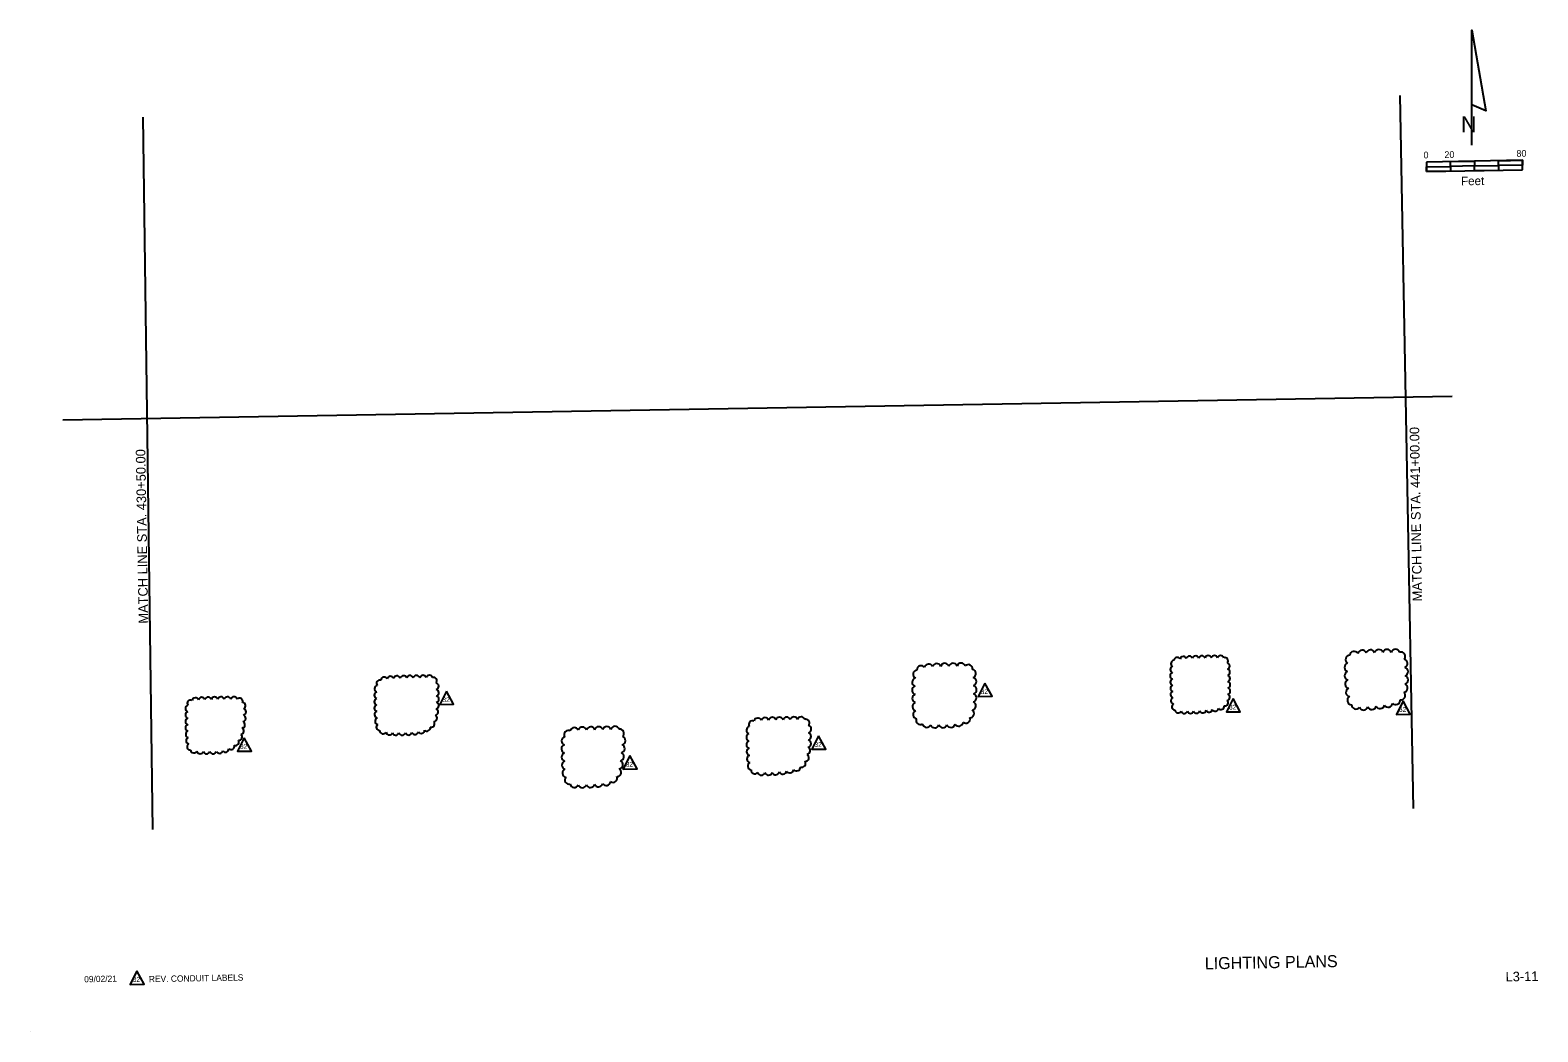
# Model space of a CAD drawing. Extents: x 921361 to 922617, y 636610 to 637445.
import ezdxf

# ---------------------------------------------------------------- set-up
doc = ezdxf.new("R2010")
doc.units = 0
for name, color, linetype in [('ActivePointCell_dp', 7, 'Continuous'), ('AdhocPoint_dp', 7, 'Continuous'), ('Cloud_dp', 7, 'Continuous'), ('MatchLines_dp', 7, 'Continuous'), ('NorthArw_dp', 7, 'Continuous'), ('Scale_dp', 7, 'Continuous'), ('TextLabel', 7, 'Continuous'), ('TextMisc', 7, 'Continuous'), ('TextNotes', 7, 'Continuous'), ('TextShtNo', 7, 'Continuous')]:
    doc.layers.add(name, color=color, linetype=linetype)

msp = doc.modelspace()

# ---------------------------------------------------------------- linework, layer by layer
at = {"layer": 'ActivePointCell_dp'}
msp.add_line((922545.7, 637139.8), (921387.8, 637119.9), dxfattribs=at)
at = {"layer": 'AdhocPoint_dp'}
msp.add_line((921360.5, 636610.2), (921360.5, 636610.2), dxfattribs=at)
at = {"layer": 'Cloud_dp'}
for points in [[(921707.6, 636894.2), (921702, 636883), (921713.5, 636883.2)], [(922156.2, 636900.9), (922150.6, 636889.7), (922162.2, 636889.9)], [(922363.2, 636888), (922357.6, 636876.8), (922369.1, 636877)], [(922504.8, 636886), (922499.3, 636874.8), (922510.8, 636875)], [(921538.9, 636855.3), (921533.3, 636844.1), (921544.9, 636844.2)], [(922017.7, 636856.9), (922012.1, 636845.7), (922023.7, 636845.9)], [(921860.4, 636840.4), (921854.8, 636829.2), (921866.4, 636829.4)]]:
    msp.add_lwpolyline(points, close=True, dxfattribs=at)
for centre, radius, start, end in [((922464, 636923.7), 3.64, 30.1798, 175.1798), ((922470.7, 636924.7), 3.64, 21.6099, 166.6099), ((922477.6, 636925), 3.64, 19.0739, 164.0739), ((922484.6, 636925.2), 3.64, 18.4841, 163.4841), ((922491.5, 636925.3), 3.64, 18.4841, 163.4841), ((922498.5, 636925.4), 3.64, 18.4841, 163.4841), ((922503, 636923.1), 3.64, 322.1453, 107.1453), ((922103.1, 636911.8), 3.56, 36.9318, 181.9318), ((922109.4, 636913.2), 3.56, 22.7645, 167.7645), ((922116.1, 636913.6), 3.56, 19.3571, 164.3571), ((922122.9, 636913.8), 3.56, 18.4841, 163.4841), ((922129.7, 636913.9), 3.56, 18.4841, 163.4841), ((922136.5, 636914), 3.56, 18.4841, 163.4841), ((922142.5, 636912.7), 3.56, 352.2854, 137.2854), ((922313.5, 636912.1), 2.74, 106.6056, 251.6056), ((922314.1, 636917.1), 2.74, 95.2077, 240.2077), ((922316.5, 636919.6), 2.74, 29.5227, 174.5227), ((922321.6, 636920.3), 2.74, 22.0992, 167.0992), ((922326.8, 636920.6), 2.74, 19.9037, 164.9037), ((922332, 636920.8), 2.74, 18.7453, 163.7453), ((922337.2, 636920.9), 2.74, 18.4841, 163.4841), ((922342.4, 636921), 2.74, 18.4841, 163.4841), ((922347.6, 636921.1), 2.74, 18.4841, 163.4841), ((922352.8, 636921.1), 2.74, 18.4841, 163.4841), ((922356.2, 636919.4), 2.74, 321.0005, 106.0005), ((922357.6, 636915), 2.74, 289.5103, 74.5103), ((922459.6, 636913.9), 3.64, 107.3116, 252.3116), ((922460.5, 636920.4), 3.64, 91.6372, 236.6372), ((922504.9, 636917.3), 3.64, 290.4209, 75.4209), ((922505.3, 636910.4), 3.64, 289.9256, 74.9256), ((921652, 636900.6), 2.83, 73.5324, 218.5324), ((921655.7, 636903), 2.84, 28.2478, 173.2478), ((921660.9, 636903.7), 2.83, 22.418, 167.418), ((921666.3, 636904.1), 2.83, 20.0853, 165.0853), ((921671.7, 636904.2), 2.83, 18.771, 163.771), ((921677.1, 636904.4), 2.83, 18.4841, 163.4841), ((921682.5, 636904.4), 2.83, 18.4841, 163.4841), ((921687.9, 636904.5), 2.83, 18.4841, 163.4841), ((921693.3, 636904.6), 2.83, 18.4841, 163.4841), ((921696.7, 636902.8), 2.83, 320.3694, 105.3694), ((921698.2, 636898.3), 2.83, 289.3685, 74.3685), ((922099.2, 636901.6), 3.56, 105.3663, 250.3663), ((922100, 636908.2), 3.56, 96.486, 241.486), ((922145.2, 636908.8), 3.56, 292.6182, 77.6182), ((922145.6, 636902.1), 3.56, 289.5181, 74.5181), ((922313.4, 636906.9), 2.74, 107.7156, 252.7156), ((922313.5, 636901.7), 2.74, 108.2731, 253.2731), ((922357.8, 636909.8), 2.74, 289.5103, 74.5103), ((922357.9, 636904.6), 2.74, 289.228, 74.228), ((922358, 636899.4), 2.74, 288.0027, 73.0027), ((922459.7, 636907), 3.64, 109.9491, 254.9491), ((922460.1, 636900.1), 3.64, 111.5337, 256.5337), ((922505.4, 636903.5), 3.64, 286.7675, 71.7675), ((921498.2, 636885.8), 2.82, 22.4167, 167.4167), ((921503.5, 636886.2), 2.82, 19.9475, 164.9475), ((921508.9, 636886.4), 2.82, 18.8576, 163.8576), ((921514.3, 636886.5), 2.82, 18.4841, 163.4841), ((921519.6, 636886.6), 2.82, 18.4841, 163.4841), ((921525, 636886.6), 2.82, 18.4841, 163.4841), ((921530.4, 636886.7), 2.82, 18.4841, 163.4841), ((921650.2, 636890.7), 2.83, 106.1055, 251.1055), ((921650.4, 636896.1), 2.83, 102.597, 247.597), ((921698.3, 636892.9), 2.83, 289.363, 74.363), ((921698.4, 636887.5), 2.83, 287.8949, 72.8949), ((922099.1, 636894.9), 3.56, 107.5915, 252.5915), ((922099.2, 636888.1), 3.56, 108.7605, 253.7605), ((922145.7, 636888.6), 3.56, 285.3566, 70.3566), ((922145.8, 636895.3), 3.56, 287.9842, 72.9842), ((922313.6, 636896.5), 2.74, 108.789, 253.789), ((922313.7, 636891.3), 2.74, 109.6972, 254.6972), ((922314, 636886.1), 2.74, 111.4666, 256.4666), ((922357.7, 636889), 2.74, 282.053, 67.053), ((922358, 636894.2), 2.74, 286.0076, 71.0076), ((922460.8, 636893.2), 3.64, 114.1871, 259.1871), ((922462, 636886.5), 3.64, 122.1504, 267.1504), ((922503, 636890.6), 3.64, 259.1914, 44.1914), ((922504.9, 636896.7), 3.64, 280.4674, 65.4674), ((921492.7, 636874.3), 2.82, 107.7468, 252.7468), ((921492.7, 636879.7), 2.82, 106.561, 251.561), ((921494.3, 636883.9), 2.82, 66.4572, 211.4572), ((921534.9, 636885.5), 2.82, 345.7741, 130.7741), ((921537.3, 636882), 2.82, 298.4484, 83.4484), ((921537.7, 636876.9), 2.82, 285.4432, 70.4432), ((921650.1, 636885.3), 2.83, 107.7278, 252.7278), ((921650.2, 636880), 2.83, 108.8515, 253.8515), ((921650.4, 636874.6), 2.83, 110.4768, 255.4768), ((921697.8, 636876.8), 2.83, 280.118, 65.118), ((921698.3, 636882.1), 2.83, 284.6737, 69.6737), ((922099.4, 636881.3), 3.56, 110.059, 255.059), ((922099.9, 636874.6), 3.56, 113.2644, 258.2644), ((922143.7, 636875.5), 3.56, 269.162, 54.162), ((922145.2, 636881.9), 3.56, 280.7068, 65.7068), ((922314.8, 636881.1), 2.74, 121.3339, 266.3339), ((922317.3, 636878.7), 2.74, 187.4829, 332.4829), ((922322.4, 636878.2), 2.74, 196.6533, 341.6533), ((922327.6, 636878.3), 2.74, 199.0023, 344.0023), ((922332.8, 636878.4), 2.74, 200.2389, 345.2389), ((922338, 636878.8), 2.74, 201.6086, 346.6086), ((922343.1, 636879.3), 2.74, 204.3652, 349.3652), ((922348.2, 636880.1), 2.74, 209.0913, 354.0913), ((922353, 636881.6), 2.74, 219.9462, 4.9462), ((922356.3, 636884.5), 2.74, 258.9336, 43.9336), ((922465.5, 636882.9), 3.64, 179.8279, 324.8279), ((922471.9, 636882), 3.64, 199.5875, 344.5875), ((922478.8, 636882.4), 3.64, 202.49, 347.49), ((922485.6, 636883.2), 3.64, 204.7964, 349.7964), ((922492.4, 636884.4), 3.64, 210.2585, 355.2585), ((922498.7, 636886.5), 3.64, 222.8245, 7.8245), ((921492.7, 636868.9), 2.82, 108.2664, 253.2664), ((921492.8, 636863.6), 2.82, 108.7679, 253.7679), ((921535.9, 636861), 2.82, 275.8999, 60.8999), ((921536.8, 636866.2), 2.82, 280.3387, 65.3387), ((921537.4, 636871.5), 2.82, 282.0867, 67.0867), ((921650.8, 636869.2), 2.83, 113.5832, 258.5832), ((921651.9, 636864.1), 2.84, 125.5477, 270.5477), ((921691.3, 636863.7), 2.83, 226.3089, 11.3089), ((921694.8, 636867), 2.83, 254.5692, 39.5692), ((921696.8, 636871.6), 2.83, 273.1433, 58.1433), ((921814.2, 636860.2), 3.55, 22.8121, 167.8121), ((921820.9, 636860.7), 3.55, 19.8729, 164.8729), ((921827.7, 636860.9), 3.55, 18.7368, 163.7368), ((921834.4, 636861), 3.55, 18.4841, 163.4841), ((921841.2, 636861.1), 3.55, 18.4841, 163.4841), ((921848, 636861.3), 3.55, 18.4841, 163.4841), ((921960.7, 636861.7), 3.16, 105.2574, 250.2574), ((921962.6, 636866.3), 3.16, 65.4586, 210.4586), ((921967, 636868.6), 3.16, 23.0122, 168.0122), ((921973, 636869), 3.16, 20.1768, 165.1768), ((921979, 636869.2), 3.16, 18.94, 163.94), ((921985, 636869.3), 3.16, 18.485, 163.485), ((921991.1, 636869.4), 3.16, 18.4841, 163.4841), ((921997.1, 636869.5), 3.16, 18.4841, 163.4841), ((922003.1, 636869.6), 3.16, 18.4841, 163.4841), ((922006.9, 636867.6), 3.16, 319.3181, 104.3181), ((922008.4, 636862.5), 3.16, 287.3997, 72.3997), ((922102.4, 636869.8), 3.56, 157.0473, 302.0473), ((922107.8, 636867.5), 3.56, 192.263, 337.263), ((922114.5, 636867.1), 3.56, 196.5296, 341.5296), ((922121.2, 636867.2), 3.56, 198.75, 343.75), ((922127.9, 636867.5), 3.56, 202.5939, 347.5939), ((922134.5, 636868.5), 3.56, 210.0847, 355.0847), ((922140.3, 636871), 3.56, 230.7482, 15.7482), ((921493, 636858.2), 2.82, 109.8016, 254.8016), ((921493.3, 636852.9), 2.82, 111.8433, 256.8433), ((921531.7, 636851.7), 2.82, 248.1796, 33.1796), ((921534.4, 636856), 2.82, 264.1119, 49.1119), ((921654.7, 636861.4), 2.83, 181.7938, 326.7938), ((921659.9, 636860.5), 2.83, 193.4288, 338.4288), ((921665.2, 636860.3), 2.83, 196.3307, 341.3307), ((921670.6, 636860.2), 2.83, 197.8463, 342.8463), ((921676, 636860.4), 2.83, 199.9242, 344.9242), ((921681.3, 636860.8), 2.83, 204.4951, 349.4951), ((921686.5, 636861.8), 2.83, 211.9917, 356.9917), ((921807, 636852.7), 3.55, 105.6871, 250.6871), ((921809.1, 636857.8), 3.55, 62.8257, 207.8257), ((921851.9, 636858.9), 3.55, 314.2673, 99.2673), ((921853.1, 636853), 3.55, 282.906, 67.906), ((921960.6, 636855.7), 3.16, 107.3482, 252.3482), ((921960.6, 636849.7), 3.16, 108.2676, 253.2676), ((922008.2, 636850.5), 3.16, 284.6241, 69.6241), ((922008.3, 636856.5), 3.16, 287.2509, 72.2509), ((921494.2, 636847.8), 2.82, 124.5456, 269.5456), ((921497, 636845.4), 2.82, 188.135, 333.135), ((921502.3, 636844.8), 2.82, 195.2009, 340.2009), ((921507.6, 636844.7), 2.82, 197.1531, 342.1531), ((921513, 636844.7), 2.82, 198.2532, 343.2532), ((921518.3, 636845.1), 2.82, 203.8548, 348.8548), ((921523.3, 636846.1), 2.82, 215.0742, 0.0742), ((921528, 636848.3), 2.82, 230.4315, 15.4315), ((921806.9, 636846), 3.55, 108.4841, 253.4841), ((921807, 636839.3), 3.55, 108.4841, 253.4841), ((921851.9, 636839.6), 3.55, 281.5185, 66.5185), ((921852.5, 636846.3), 3.55, 282.8541, 67.8541), ((921960.8, 636843.7), 3.16, 109.2906, 254.2906), ((921961.1, 636837.7), 3.16, 111.2776, 256.2776), ((922006.4, 636838.8), 3.16, 270.331, 55.331), ((922007.6, 636844.6), 3.16, 279.5751, 64.5751), ((921807.2, 636832.5), 3.55, 108.7176, 253.7176), ((921807.7, 636825.9), 3.55, 114.82, 259.82), ((921849.6, 636826.5), 3.55, 270.8983, 55.8983), ((921851, 636832.9), 3.55, 278.539, 63.539), ((921961.7, 636831.8), 3.16, 117.0195, 262.0195), ((921964.5, 636828.4), 3.16, 174.9065, 319.9065), ((921969.9, 636827.2), 3.16, 197.0357, 342.0357), ((921975.9, 636827.3), 3.16, 199.5755, 344.5755), ((921981.9, 636827.6), 3.16, 200.9456, 345.9456), ((921987.9, 636828.1), 3.16, 203.9584, 348.9584), ((921993.7, 636829.1), 3.16, 209.4298, 354.4298), ((921999.3, 636830.8), 3.16, 220.2081, 5.2081), ((922003.7, 636834), 3.16, 246.8195, 31.8195), ((921809.7, 636820.1), 3.55, 140.0491, 285.0491), ((921814.1, 636817.4), 3.55, 192.035, 337.035), ((921820.8, 636817.2), 3.55, 198.641, 343.641), ((921827.5, 636817.4), 3.55, 200.6558, 345.6558), ((921834.2, 636817.9), 3.55, 203.2589, 348.2589), ((921840.7, 636819), 3.55, 210.8383, 355.8383), ((921846.3, 636821.7), 3.55, 235.3792, 20.3792)]:
    msp.add_arc(centre, radius, start, end, dxfattribs=at)
at = {"layer": 'MatchLines_dp'}
for p, q in [((922502.2, 637390.5), (922513.3, 636796.3)), ((921454.5, 637372.5), (921462.4, 636778.8))]:
    msp.add_line(p, q, dxfattribs=at)
at = {"layer": 'NorthArw_dp'}
msp.add_line((922562.2, 637349), (922562.2, 637445), dxfattribs=at)
msp.add_lwpolyline([(922562.2, 637382.6), (922562.2, 637445), (922573.7, 637377.8)], close=True, dxfattribs=at)
at = {"layer": 'Scale_dp'}
for p, q in [((922604.3, 637336.5), (922524.3, 637335.1)), ((922524.3, 637335.1), (922524.4, 637327.1)), ((922524.4, 637327.1), (922604.4, 637328.5)), ((922604.4, 637328.5), (922604.3, 637336.5))]:
    msp.add_line(p, q, dxfattribs=at)
for points in [[(922524.4, 637327.1), (922524.4, 637331.1), (922544.4, 637331.4), (922544.4, 637327.4)], [(922544.4, 637331.4), (922544.3, 637335.4), (922564.3, 637335.8), (922564.4, 637331.8)], [(922564.4, 637327.8), (922564.4, 637331.8), (922584.4, 637332.1), (922584.4, 637328.1)], [(922584.4, 637332.1), (922584.3, 637336.1), (922604.3, 637336.5), (922604.4, 637332.5)]]:
    msp.add_lwpolyline(points, close=True, dxfattribs=at)
at = {"layer": 'TextNotes'}
msp.add_lwpolyline([(921449.5, 636661), (921443.9, 636649.8), (921455.5, 636650)], close=True, dxfattribs=at)

# ---------------------------------------------------------------- texts
at = {"layer": 'Cloud_dp'}
for p in [(921704.2, 636885), (922152.8, 636891.7), (922359.8, 636878.8), (922501.4, 636876.8), (922014.3, 636847.7), (921535.5, 636846.1), (921857, 636831.2)]:
    msp.add_text('32', height=3.94, rotation=0.9841, dxfattribs=at).set_placement(p)
at = {"layer": 'MatchLines_dp'}
for s, p in [('MATCH LINE STA. 441+00.00', (922520.7, 636969)), ('MATCH LINE STA. 430+50.00', (921459, 636950.5))]:
    msp.add_text(s, height=8, rotation=90.9841, dxfattribs=at).set_placement(p)
at = {"layer": 'NorthArw_dp'}
msp.add_text('N', height=13.4, dxfattribs=at).set_placement((922553.1, 637359.8))
at = {"layer": 'Scale_dp'}
for s, height, p in [('0', 5.6, (922521.9, 637338.1)), ('20', 5.6, (922539.3, 637338.4)), ('80', 5.6, (922599.3, 637339.4)), ('Feet', 7.2, (922553.2, 637315.6))]:
    msp.add_text(s, height=height, rotation=0.9841, dxfattribs=at).set_placement(p)
at = {"layer": 'TextLabel'}
for s, p in [('09/02/21', (921405.6, 636651.5)), ('REV. CONDUIT LABELS', (921459.5, 636651.6))]:
    msp.add_text(s, height=5.25, rotation=0.9841, dxfattribs=at).set_placement(p)
at = {"layer": 'TextMisc'}
msp.add_text('        LIGHTING PLANS         ', height=10, rotation=0.9841, dxfattribs=at).set_placement((922309.9, 636661.8))
at = {"layer": 'TextNotes'}
msp.add_text('32', height=3.94, rotation=0.9841, dxfattribs=at).set_placement((921446.1, 636651.8))
at = {"layer": 'TextShtNo'}
msp.add_text('L3-11 ', height=8, rotation=0.9841, dxfattribs=at).set_placement((922590.3, 636652.2))

doc.saveas('drawing.dxf')
